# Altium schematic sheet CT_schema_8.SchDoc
size 278 x 170 mm
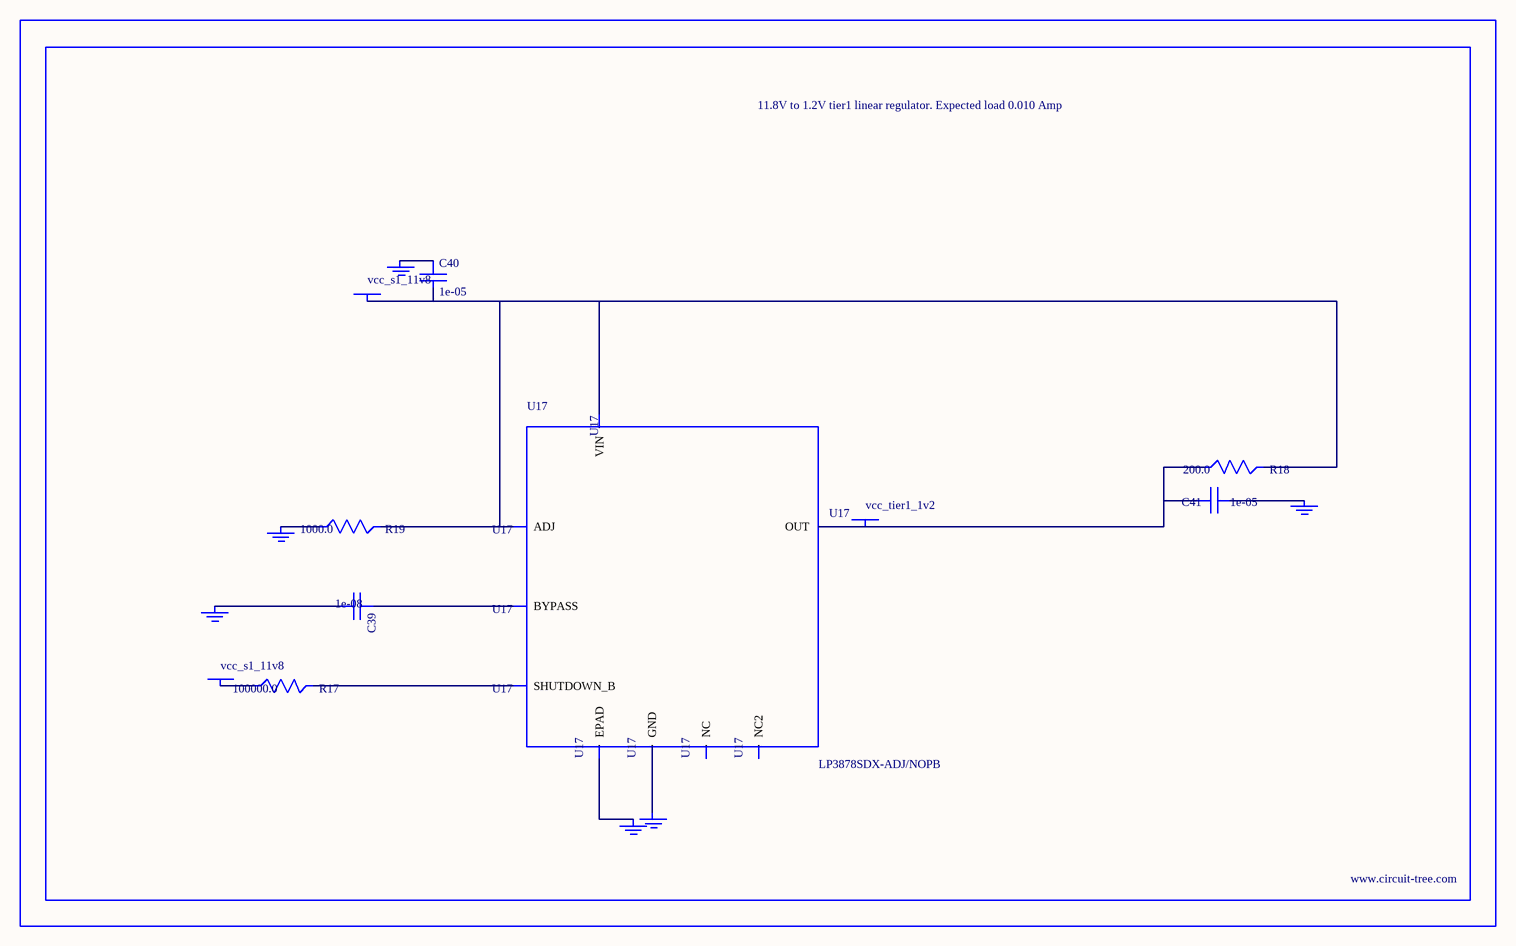
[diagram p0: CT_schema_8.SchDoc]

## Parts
BORDER7  (no value)
C39  1e-08  [C0402]
C40  1e-05  [C1210]
C41  1e-05  [C0805]
GND_INSTANCE_7_0  (no value)
GND_INSTANCE_7_1  (no value)
GND_INSTANCE_7_2  (no value)
GND_INSTANCE_7_3  (no value)
GND_INSTANCE_7_4  (no value)
GND_INSTANCE_7_5  (no value)
POWER_INSTANCE_7_0  vcc_s1_11v8
POWER_INSTANCE_7_1  vcc_s1_11v8
POWER_INSTANCE_7_2  vcc_tier1_1v2
R17  100000.0  [R0603]
R18  200.0  [R0603]
R19  1000.0  [R0603]
U17  LP3878SDX-ADJ/NOPB  [WSON-8]

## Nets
NetC39_1: C39.1 U17.1(BYPASS)
NetC39_2: C39.2 GND_INSTANCE_7_0.0(GND)
NetC40_1: C40.1 GND_INSTANCE_7_1.0(GND)
NetC40_2: C40.2 POWER_INSTANCE_7_0.0(PWR) R18.2 R19.2 U17.4(VIN) U17.6(ADJ)
NetC41_1: C41.1 GND_INSTANCE_7_2.0(GND)
NetC41_2: C41.2 POWER_INSTANCE_7_2.0(PWR) R18.1 U17.5(OUT)
NetGND_INSTANCE_7_3_0: GND_INSTANCE_7_3.0(GND) R19.1
NetGND_INSTANCE_7_4_0: GND_INSTANCE_7_4.0(GND) U17.PAD(EPAD)
NetGND_INSTANCE_7_5_0: GND_INSTANCE_7_5.0(GND) U17.3(GND)
NetPOWER_INSTANCE_7_1_0: POWER_INSTANCE_7_1.0(PWR) R17.1
NetR17_2: R17.2 U17.8(SHUTDOWN_B)

Not connected (* = marked no-connect by the designer): U17 2(NC) 7(NC2)

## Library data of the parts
BORDER7 = BORDER_PAGE7
C39 = C0402C103K3RAC
C40 = C1210C106K5PACTU
C41 = GRM219R60J106ME19D
GND_INSTANCE_7_0-GND_INSTANCE_7_5 = GND
POWER_INSTANCE_7_0-POWER_INSTANCE_7_2 = PWR
R17 = RC0603JR-07100KL
R18 = RC0603JR-07200RL
R19 = RC0603JR-071KL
